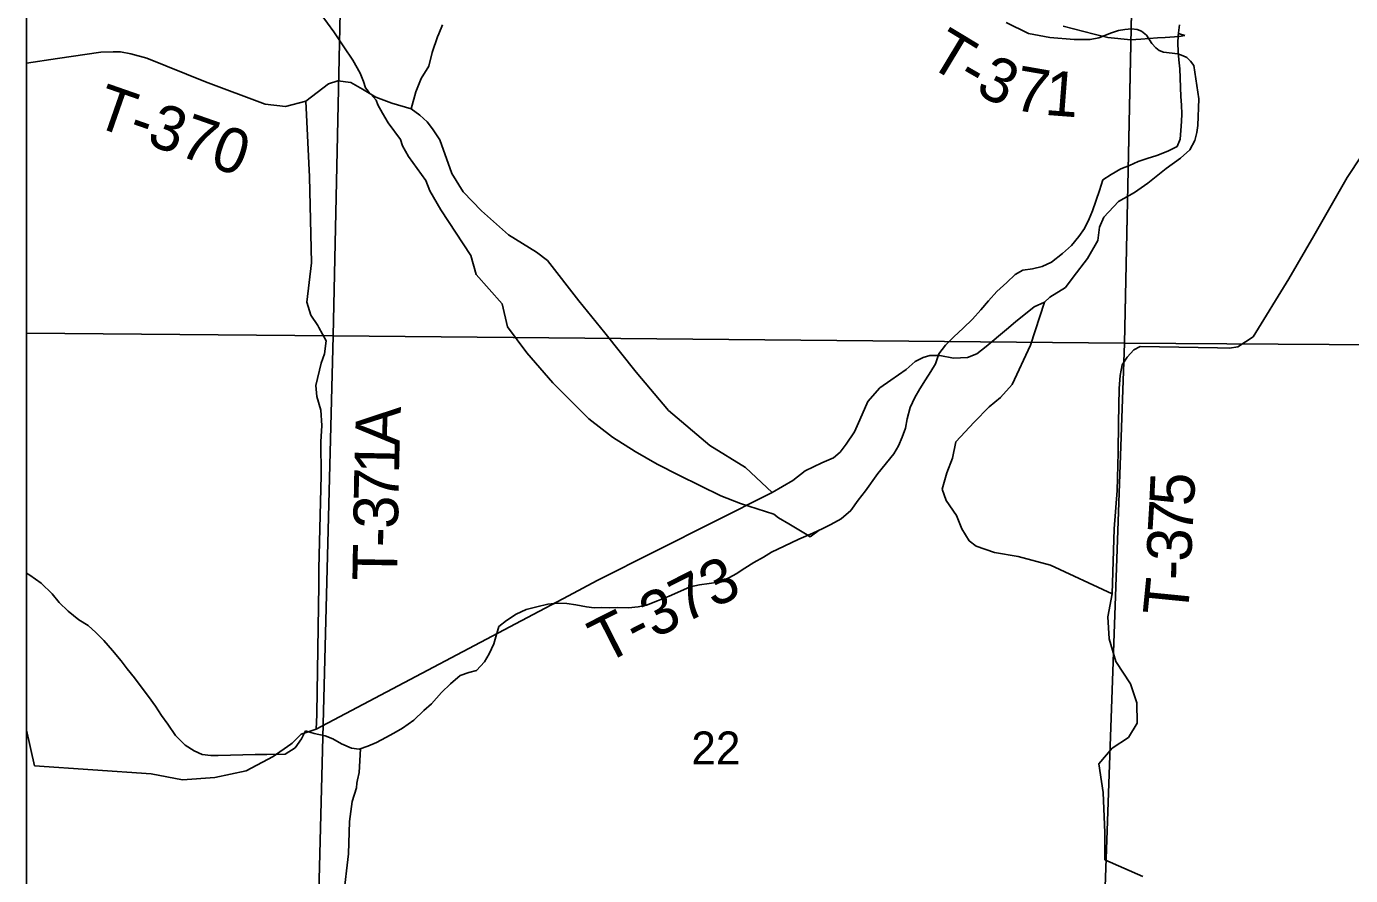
# Model space of a CAD drawing. Extents: x 2.1 to 8.9, y 14.1 to 20.9.
# Drawn here: x 2.1 to 3.78, y 16.441 to 17.519 of the extents above; entities that cross this region are included whole.
import ezdxf

# ---------------------------------------------------------------- set-up
doc = ezdxf.new("R2010")
doc.units = 0
for name, color, linetype in [('Default', 7, 'Continuous'), ('GM_X_City_Street', 7, 'Continuous'), ('GM_X_County_Road_Text', 7, 'Continuous'), ('GM_X_Interchange_Ramps', 7, 'Continuous'), ('GM_X_Minor_River_Text', 7, 'Continuous'), ('SH_Cut_Line', 7, 'Continuous'), ('SH_Data', 7, 'Continuous'), ('TX_P_Misc', 7, 'Continuous')]:
    doc.layers.add(name, color=color, linetype=linetype)

msp = doc.modelspace()

# ---------------------------------------------------------------- linework, layer by layer
at = {"layer": 'Default'}
for p, q in [((2.1, 19.1502), (2.1, 14.1)), ((2.1, 18.1363), (2.1, 17.1299)), ((2.4891, 17.1265), (2.5107, 18.1291)), ((2.1, 17.1299), (2.4891, 17.1265)), ((2.1, 17.1299), (2.1, 16.1234)), ((2.4891, 17.1265), (2.1, 17.1299)), ((2.4631, 16.1204), (2.4891, 17.1265))]:
    msp.add_line(p, q, dxfattribs=at)
at = {"layer": 'GM_X_City_Street'}
for p, q in [((2.6217, 17.5059), (2.6233, 17.5099)), ((2.6233, 17.5099), (2.6278, 17.521)), ((3.3715, 17.5102), (3.3432, 17.5241)), ((3.3989, 17.5049), (3.3715, 17.5102)), ((3.4771, 17.5108), (3.461, 17.5045)), ((3.4861, 17.5139), (3.4771, 17.5108)), ((3.494, 17.5153), (3.4861, 17.5139)), ((3.5026, 17.5161), (3.494, 17.5153)), ((3.5097, 17.5154), (3.5026, 17.5161)), ((3.5153, 17.5131), (3.5097, 17.5154)), ((3.5213, 17.5079), (3.5153, 17.5131)), ((2.615, 17.4862), (2.6217, 17.5059)), ((3.4297, 17.5025), (3.3989, 17.5049)), ((3.4498, 17.5025), (3.4297, 17.5025)), ((3.461, 17.5045), (3.4498, 17.5025)), ((3.5282, 17.4974), (3.5213, 17.5079)), ((3.5335, 17.4919), (3.5282, 17.4974)), ((2.1394, 17.4785), (2.1, 17.4724)), ((2.1944, 17.4865), (2.1394, 17.4785)), ((2.2101, 17.487), (2.1944, 17.4865)), ((2.2193, 17.4867), (2.2101, 17.487)), ((2.2326, 17.4843), (2.2193, 17.4867)), ((2.2526, 17.479), (2.2326, 17.4843)), ((2.3273, 17.4489), (2.2526, 17.479)), ((2.6105, 17.4685), (2.615, 17.4862)), ((3.5374, 17.4887), (3.5335, 17.4919)), ((3.5432, 17.4866), (3.5374, 17.4887)), ((3.5614, 17.4844), (3.5432, 17.4866)), ((3.5678, 17.4819), (3.5614, 17.4844)), ((3.5725, 17.4795), (3.5678, 17.4819)), ((3.5774, 17.4749), (3.5725, 17.4795)), ((2.6009, 17.4529), (2.6105, 17.4685)), ((3.5816, 17.4694), (3.5774, 17.4749)), ((3.5879, 17.4274), (3.5816, 17.4694)), ((2.4031, 17.4204), (2.3273, 17.4489)), ((2.4835, 17.4462), (2.4545, 17.4244)), ((2.4951, 17.4499), (2.4835, 17.4462)), ((2.5118, 17.4479), (2.4951, 17.4499)), ((2.5265, 17.4395), (2.5118, 17.4479)), ((2.5941, 17.4362), (2.6009, 17.4529)), ((2.5434, 17.4293), (2.5265, 17.4395)), ((2.5635, 17.4218), (2.5434, 17.4293)), ((2.5883, 17.4145), (2.5941, 17.4362)), ((3.5867, 17.3933), (3.5879, 17.4274)), ((2.4289, 17.4175), (2.4031, 17.4204)), ((2.4545, 17.4244), (2.4289, 17.4175)), ((2.4591, 17.3283), (2.4545, 17.4244)), ((2.5883, 17.4145), (2.5635, 17.4218)), ((2.5993, 17.4066), (2.5883, 17.4145)), ((2.6084, 17.3978), (2.5993, 17.4066)), ((2.6154, 17.3892), (2.6084, 17.3978)), ((3.5853, 17.3844), (3.5867, 17.3933)), ((2.6248, 17.3751), (2.6154, 17.3892)), ((2.6397, 17.3322), (2.6248, 17.3751)), ((3.5829, 17.3741), (3.5853, 17.3844)), ((3.5647, 17.3517), (3.5766, 17.3623)), ((3.5766, 17.3623), (3.5829, 17.3741)), ((3.5466, 17.3389), (3.5647, 17.3517)), ((3.7763, 17.3273), (3.7944, 17.3548)), ((2.4617, 17.2192), (2.4591, 17.3283)), ((2.654, 17.3092), (2.6397, 17.3322)), ((3.5231, 17.32), (3.5466, 17.3389)), ((3.7337, 17.2533), (3.7763, 17.3273)), ((2.6776, 17.2851), (2.654, 17.3092)), ((3.4859, 17.2969), (3.5061, 17.3084)), ((3.5061, 17.3084), (3.5231, 17.32)), ((3.4675, 17.2768), (3.4859, 17.2969)), ((2.7116, 17.2547), (2.6776, 17.2851)), ((3.4617, 17.2644), (3.4675, 17.2768)), ((3.4598, 17.2472), (3.4617, 17.2644)), ((2.7471, 17.2326), (2.7116, 17.2547)), ((3.4464, 17.2246), (3.4598, 17.2472)), ((3.7021, 17.1987), (3.7337, 17.2533)), ((2.7611, 17.2218), (2.7471, 17.2326)), ((3.4285, 17.201), (3.4464, 17.2246)), ((2.4556, 17.1692), (2.4617, 17.2192)), ((2.8011, 17.1708), (2.7611, 17.2218)), ((3.4185, 17.1876), (3.4285, 17.201)), ((3.6567, 17.1251), (3.7021, 17.1987)), ((3.3919, 17.1689), (3.3986, 17.1753)), ((3.3986, 17.1753), (3.4185, 17.1876)), ((2.4609, 17.1527), (2.4556, 17.1692)), ((2.8338, 17.1301), (2.8011, 17.1708)), ((3.3787, 17.1631), (3.3553, 17.1442)), ((3.3742, 17.1145), (3.3919, 17.1689)), ((3.3919, 17.1689), (3.3787, 17.1631)), ((2.4698, 17.1395), (2.4609, 17.1527)), ((3.3553, 17.1442), (3.3439, 17.1343)), ((2.4711, 17.1371), (2.4698, 17.1395)), ((2.4805, 17.1198), (2.4711, 17.1371)), ((2.8737, 17.0804), (2.8338, 17.1301)), ((3.3439, 17.1343), (3.3179, 17.1129)), ((3.6375, 17.1124), (3.6567, 17.1251)), ((2.4782, 17.1033), (2.4805, 17.1198)), ((3.3179, 17.1129), (3.3063, 17.1036)), ((3.3511, 17.0644), (3.3742, 17.1145)), ((3.4968, 17.0992), (3.5054, 17.1087)), ((3.5054, 17.1087), (3.5133, 17.1127)), ((3.5133, 17.1127), (3.6117, 17.111)), ((3.6117, 17.111), (3.6266, 17.1107)), ((3.6266, 17.1107), (3.6375, 17.1124)), ((2.4671, 17.0633), (2.4738, 17.0917)), ((2.4738, 17.0917), (2.4782, 17.1033)), ((3.2279, 17.0937), (3.2165, 17.0837)), ((3.238, 17.099), (3.2279, 17.0937)), ((3.2465, 17.1013), (3.238, 17.099)), ((3.2592, 17.1013), (3.2465, 17.1013)), ((3.2764, 17.0981), (3.2592, 17.1013)), ((3.2943, 17.0988), (3.2764, 17.0981)), ((3.3063, 17.1036), (3.2943, 17.0988)), ((3.488, 17.0758), (3.4905, 17.0895)), ((3.4905, 17.0895), (3.4968, 17.0992)), ((2.915, 17.0316), (2.8737, 17.0804)), ((3.2165, 17.0837), (3.197, 17.0702)), ((3.4867, 17.0596), (3.488, 17.0758)), ((2.4684, 17.0493), (2.4671, 17.0633)), ((3.1831, 17.0605), (3.1679, 17.0431)), ((3.197, 17.0702), (3.1831, 17.0605)), ((3.3361, 17.0482), (3.3511, 17.0644)), ((3.4861, 17.0159), (3.4867, 17.0596)), ((2.4734, 17.032), (2.4684, 17.0493)), ((3.1679, 17.0431), (3.1576, 17.0199)), ((3.3219, 17.0362), (3.3361, 17.0482)), ((2.475, 17.0127), (2.4734, 17.032)), ((2.9674, 16.9872), (2.915, 17.0316)), ((3.3027, 17.0167), (3.3219, 17.0362)), ((2.4736, 16.9917), (2.475, 17.0127)), ((3.1576, 17.0199), (3.1509, 17.0045)), ((3.2796, 16.9917), (3.3027, 17.0167)), ((3.4855, 16.9781), (3.4861, 17.0159)), ((2.4739, 16.9495), (2.4736, 16.9917)), ((3.1401, 16.9887), (3.1328, 16.9785)), ((3.1509, 17.0045), (3.1401, 16.9887)), ((3.2752, 16.9712), (3.2796, 16.9917)), ((3.0126, 16.9593), (2.9674, 16.9872)), ((3.1328, 16.9785), (3.1241, 16.9715)), ((3.4841, 16.9301), (3.4855, 16.9781)), ((3.0465, 16.9274), (3.0126, 16.9593)), ((3.1094, 16.9649), (3.0883, 16.9548)), ((3.1241, 16.9715), (3.1094, 16.9649)), ((3.2681, 16.9524), (3.2752, 16.9712)), ((2.4712, 16.8304), (2.4739, 16.9495)), ((3.0725, 16.9426), (3.0465, 16.9274)), ((3.0883, 16.9548), (3.0725, 16.9426)), ((3.262, 16.9316), (3.2681, 16.9524)), ((2.8242, 16.8156), (3.0465, 16.9274)), ((3.2673, 16.9171), (3.262, 16.9316)), ((3.4805, 16.8814), (3.4841, 16.9301)), ((3.2802, 16.8984), (3.2673, 16.9171)), ((3.287, 16.8814), (3.2802, 16.8984)), ((3.2966, 16.8659), (3.287, 16.8814)), ((3.478, 16.799), (3.4805, 16.8814)), ((3.3053, 16.8593), (3.2966, 16.8659)), ((3.3287, 16.8512), (3.3053, 16.8593)), ((3.3584, 16.846), (3.3287, 16.8512)), ((3.3995, 16.8354), (3.3584, 16.846)), ((2.4709, 16.8102), (2.4712, 16.8304)), ((3.478, 16.799), (3.3995, 16.8354)), ((2.4687, 16.647), (2.4709, 16.8102)), ((2.7877, 16.7963), (2.8242, 16.8156)), ((2.4675, 16.627), (2.7877, 16.7963)), ((3.4723, 16.7698), (3.478, 16.799)), ((3.4739, 16.7415), (3.4723, 16.7698)), ((3.4824, 16.7127), (3.4739, 16.7415)), ((3.5011, 16.6844), (3.4824, 16.7127)), ((3.5091, 16.6603), (3.5011, 16.6844)), ((3.5097, 16.6347), (3.5091, 16.6603)), ((2.4675, 16.627), (2.4685, 16.6452)), ((2.4685, 16.6452), (2.4687, 16.647)), ((2.1, 16.6259), (2.1102, 16.5805)), ((2.4395, 16.6115), (2.4487, 16.6205)), ((2.4487, 16.6205), (2.4675, 16.627)), ((3.4984, 16.6165), (3.5097, 16.6347)), ((2.413, 16.5924), (2.4356, 16.6081)), ((2.4356, 16.6081), (2.4372, 16.6093)), ((2.4372, 16.6093), (2.4395, 16.6115)), ((3.4609, 16.583), (3.4778, 16.6029)), ((3.4778, 16.6029), (3.4984, 16.6165)), ((2.3789, 16.5742), (2.413, 16.5924)), ((2.1102, 16.5805), (2.2583, 16.5702)), ((2.2583, 16.5702), (2.2978, 16.5627)), ((2.339, 16.5658), (2.3789, 16.5742)), ((3.4643, 16.5605), (3.4609, 16.583)), ((2.2978, 16.5627), (2.339, 16.5658)), ((3.4665, 16.5468), (3.4643, 16.5605)), ((3.4685, 16.4953), (3.4665, 16.5468)), ((3.4685, 16.4612), (3.4685, 16.4953)), ((3.517, 16.4401), (3.4685, 16.4612))]:
    msp.add_line(p, q, dxfattribs=at)
at = {"layer": 'GM_X_Interchange_Ramps'}
for p, q in [((2.4891, 17.1265), (2.5107, 18.1291)), ((3.5154, 18.1224), (3.4934, 17.1171)), ((3.4934, 17.1171), (3.5154, 18.1224)), ((2.4631, 16.1204), (2.4891, 17.1265)), ((3.4934, 17.1171), (2.4891, 17.1265)), ((2.4891, 17.1265), (3.4934, 17.1171)), ((3.4934, 17.1171), (3.4577, 16.1051)), ((3.4577, 16.1051), (3.4934, 17.1171)), ((4.4928, 17.1099), (3.4934, 17.1171)), ((3.4934, 17.1171), (4.4928, 17.1099))]:
    msp.add_line(p, q, dxfattribs=at)
at = {"layer": 'SH_Cut_Line'}
msp.add_line((2.1, 20.9), (2.1, 14.1), dxfattribs=at)
at = {"layer": 'SH_Data'}
msp.add_line((2.1, 20.9), (2.1, 14.1), dxfattribs=at)
msp.add_line((2.1, 20.9), (2.1, 14.1), dxfattribs=at)
at = {"layer": 'TX_P_Misc'}
for p, q in [((2.4899, 17.5123), (2.474, 17.5344)), ((2.5027, 17.4931), (2.4899, 17.5123)), ((3.455, 17.5091), (3.4159, 17.5195)), ((3.5635, 17.5211), (3.5616, 17.5074)), ((3.562, 17.51), (3.5699, 17.5076)), ((2.5143, 17.4761), (2.5027, 17.4931)), ((3.4724, 17.5052), (3.455, 17.5091)), ((3.5016, 17.5019), (3.4724, 17.5052)), ((3.5144, 17.5029), (3.5016, 17.5019)), ((3.5352, 17.5047), (3.5144, 17.5029)), ((3.545, 17.5049), (3.5352, 17.5047)), ((3.5628, 17.5063), (3.545, 17.5049)), ((3.5616, 17.5074), (3.5612, 17.4979)), ((3.5612, 17.4979), (3.5615, 17.4872)), ((3.5699, 17.5076), (3.5628, 17.5063)), ((2.5233, 17.4599), (2.5143, 17.4761)), ((3.5615, 17.4872), (3.5626, 17.4766)), ((3.5626, 17.4766), (3.5637, 17.4652)), ((2.5276, 17.4493), (2.5233, 17.4599)), ((3.5637, 17.4652), (3.564, 17.4538)), ((2.5304, 17.441), (2.5276, 17.4493)), ((3.564, 17.4538), (3.5648, 17.4416)), ((2.5335, 17.4369), (2.5304, 17.441)), ((2.5439, 17.4256), (2.5335, 17.4369)), ((2.5459, 17.4196), (2.5439, 17.4256)), ((3.5648, 17.4416), (3.5651, 17.4302)), ((3.5651, 17.4302), (3.5659, 17.4192)), ((2.5518, 17.409), (2.5459, 17.4196)), ((2.5592, 17.3969), (2.5518, 17.409)), ((3.5659, 17.4192), (3.5662, 17.4082)), ((2.5746, 17.3755), (2.5592, 17.3969)), ((3.5657, 17.3986), (3.5649, 17.3872)), ((3.5662, 17.4082), (3.5657, 17.3986)), ((2.5771, 17.3675), (2.5746, 17.3755)), ((3.5641, 17.3761), (3.5603, 17.3665)), ((3.5649, 17.3872), (3.5641, 17.3761)), ((2.5848, 17.354), (2.5771, 17.3675)), ((3.5486, 17.3608), (3.5344, 17.3554)), ((3.5603, 17.3665), (3.5486, 17.3608)), ((2.6069, 17.3235), (2.5848, 17.354)), ((3.4998, 17.3425), (3.4889, 17.3384)), ((3.511, 17.3478), (3.4998, 17.3425)), ((3.5223, 17.3516), (3.511, 17.3478)), ((3.5344, 17.3554), (3.5223, 17.3516)), ((3.4766, 17.3311), (3.4661, 17.3243)), ((3.4889, 17.3384), (3.4766, 17.3311)), ((2.6117, 17.3103), (2.6069, 17.3235)), ((2.6257, 17.2861), (2.6117, 17.3103)), ((3.462, 17.3109), (3.4529, 17.2851)), ((3.4661, 17.3243), (3.462, 17.3109)), ((2.6641, 17.2282), (2.6257, 17.2861)), ((3.4486, 17.2747), (3.4426, 17.2627)), ((3.4529, 17.2851), (3.4486, 17.2747)), ((3.4426, 17.2627), (3.4356, 17.2526)), ((3.4261, 17.2412), (3.415, 17.231)), ((3.4356, 17.2526), (3.4261, 17.2412)), ((2.6709, 17.2043), (2.6641, 17.2282)), ((3.415, 17.231), (3.4009, 17.2199)), ((3.3643, 17.2096), (3.3546, 17.204)), ((3.3768, 17.2115), (3.3643, 17.2096)), ((3.3889, 17.2142), (3.3768, 17.2115)), ((3.4009, 17.2199), (3.3889, 17.2142)), ((2.7037, 17.1668), (2.6709, 17.2043)), ((3.3443, 17.1941), (3.3317, 17.1827)), ((3.3546, 17.204), (3.3443, 17.1941)), ((3.3317, 17.1827), (3.3211, 17.1706)), ((2.7106, 17.1376), (2.7037, 17.1668)), ((3.3112, 17.1592), (3.3005, 17.1474)), ((3.3211, 17.1706), (3.3112, 17.1592)), ((3.3005, 17.1474), (3.2887, 17.136)), ((2.735, 17.1049), (2.7106, 17.1376)), ((3.2768, 17.125), (3.2665, 17.1144)), ((3.2887, 17.136), (3.2768, 17.125)), ((3.2665, 17.1144), (3.2577, 17.1035)), ((2.7678, 17.0666), (2.735, 17.1049)), ((3.2536, 17.0908), (3.2478, 17.0811)), ((3.2577, 17.1035), (3.2536, 17.0908)), ((3.2478, 17.0811), (3.2409, 17.0706)), ((2.8136, 17.0209), (2.7678, 17.0666)), ((3.2336, 17.0589), (3.2275, 17.0481)), ((3.2409, 17.0706), (3.2336, 17.0589)), ((3.2275, 17.0481), (3.2214, 17.0353)), ((3.2214, 17.0353), (3.2177, 17.0211)), ((2.8438, 16.9975), (2.8136, 17.0209)), ((3.2154, 17.0092), (3.2112, 16.9977)), ((3.2177, 17.0211), (3.2154, 17.0092)), ((2.8725, 16.9793), (2.8438, 16.9975)), ((3.2112, 16.9977), (3.2066, 16.9865)), ((2.9004, 16.9634), (2.8725, 16.9793)), ((3.2008, 16.9764), (3.1803, 16.9514)), ((3.2066, 16.9865), (3.2008, 16.9764)), ((2.9278, 16.9494), (2.9004, 16.9634)), ((2.9553, 16.9361), (2.9278, 16.9494)), ((3.1803, 16.9514), (3.165, 16.9296)), ((2.9812, 16.9232), (2.9553, 16.9361)), ((3.0063, 16.9134), (2.9812, 16.9232)), ((3.165, 16.9296), (3.1555, 16.9175)), ((3.0485, 16.9), (3.0063, 16.9134)), ((3.146, 16.9047), (3.1338, 16.894)), ((3.1555, 16.9175), (3.146, 16.9047)), ((3.0543, 16.8951), (3.0485, 16.9)), ((3.0676, 16.8878), (3.0543, 16.8951)), ((3.1338, 16.894), (3.1207, 16.8867)), ((3.0886, 16.8748), (3.0676, 16.8878)), ((3.0978, 16.8757), (3.0802, 16.868)), ((3.0944, 16.8711), (3.0886, 16.8748)), ((3.1062, 16.8798), (3.0944, 16.8711)), ((3.1106, 16.8819), (3.0978, 16.8757)), ((3.1207, 16.8867), (3.1106, 16.8819)), ((3.0615, 16.8594), (3.0457, 16.8516)), ((3.0802, 16.868), (3.0615, 16.8594)), ((3.0229, 16.8387), (3.0117, 16.8315)), ((3.0353, 16.8452), (3.0229, 16.8387)), ((3.0457, 16.8516), (3.0353, 16.8452)), ((2.1041, 16.8224), (2.1, 16.8249)), ((2.1185, 16.8122), (2.1041, 16.8224)), ((3.0006, 16.824), (2.9875, 16.8171)), ((3.0117, 16.8315), (3.0006, 16.824)), ((2.1326, 16.799), (2.1185, 16.8122)), ((2.9425, 16.8077), (2.9301, 16.8023)), ((2.9542, 16.8103), (2.9425, 16.8077)), ((2.9663, 16.8118), (2.9542, 16.8103)), ((2.9777, 16.8137), (2.9663, 16.8118)), ((2.9875, 16.8171), (2.9777, 16.8137)), ((2.1413, 16.7878), (2.1326, 16.799)), ((2.1527, 16.7767), (2.1413, 16.7878)), ((2.9009, 16.79), (2.887, 16.7846)), ((2.9155, 16.7958), (2.9009, 16.79)), ((2.9301, 16.8023), (2.9155, 16.7958)), ((2.1663, 16.7658), (2.1527, 16.7767)), ((2.7216, 16.7729), (2.7093, 16.7649)), ((2.7343, 16.7791), (2.7216, 16.7729)), ((2.7475, 16.7825), (2.7343, 16.7791)), ((2.7618, 16.7856), (2.7475, 16.7825)), ((2.7747, 16.7868), (2.7618, 16.7856)), ((2.7858, 16.7864), (2.7747, 16.7868)), ((2.7972, 16.7848), (2.7858, 16.7864)), ((2.8106, 16.7822), (2.7972, 16.7848)), ((2.8205, 16.781), (2.8106, 16.7822)), ((2.83, 16.7813), (2.8205, 16.781)), ((2.8403, 16.7812), (2.83, 16.7813)), ((2.8506, 16.7816), (2.8403, 16.7812)), ((2.8639, 16.7812), (2.8506, 16.7816)), ((2.8764, 16.7824), (2.8639, 16.7812)), ((2.887, 16.7846), (2.8764, 16.7824)), ((2.1783, 16.7585), (2.1663, 16.7658)), ((2.1881, 16.7497), (2.1783, 16.7585)), ((2.6996, 16.7574), (2.693, 16.7355)), ((2.7093, 16.7649), (2.6996, 16.7574)), ((2.1983, 16.7397), (2.1881, 16.7497)), ((2.2093, 16.7267), (2.1983, 16.7397)), ((2.22, 16.7138), (2.2093, 16.7267)), ((2.687, 16.7227), (2.6812, 16.7123)), ((2.693, 16.7355), (2.687, 16.7227)), ((2.2279, 16.7037), (2.22, 16.7138)), ((2.237, 16.6922), (2.2279, 16.7037)), ((2.6812, 16.7123), (2.6713, 16.7013)), ((2.2457, 16.6807), (2.237, 16.6922)), ((2.6506, 16.6953), (2.638, 16.6847)), ((2.6615, 16.6991), (2.6506, 16.6953)), ((2.6713, 16.7013), (2.6615, 16.6991)), ((2.2548, 16.6684), (2.2457, 16.6807)), ((2.6269, 16.6736), (2.614, 16.6592)), ((2.638, 16.6847), (2.6269, 16.6736)), ((2.2636, 16.6561), (2.2548, 16.6684)), ((2.2715, 16.6442), (2.2636, 16.6561)), ((2.614, 16.6592), (2.6044, 16.6505)), ((2.2795, 16.6334), (2.2715, 16.6442)), ((2.5915, 16.6386), (2.5773, 16.6283)), ((2.6044, 16.6505), (2.5915, 16.6386)), ((2.2891, 16.6188), (2.2795, 16.6334)), ((2.4543, 16.6248), (2.4492, 16.6148)), ((2.465, 16.6217), (2.4543, 16.6248)), ((2.4792, 16.6184), (2.465, 16.6217)), ((2.5661, 16.6219), (2.556, 16.6166)), ((2.5773, 16.6283), (2.5661, 16.6219)), ((2.3012, 16.6067), (2.2891, 16.6188)), ((2.3128, 16.5994), (2.3012, 16.6067)), ((2.4409, 16.6031), (2.4282, 16.5954)), ((2.4492, 16.6148), (2.4409, 16.6031)), ((2.4888, 16.6149), (2.4792, 16.6184)), ((2.5, 16.6084), (2.4888, 16.6149)), ((2.5123, 16.603), (2.5, 16.6084)), ((2.5223, 16.6014), (2.5123, 16.603)), ((2.5332, 16.6056), (2.5223, 16.6014)), ((2.5441, 16.6101), (2.5332, 16.6056)), ((2.556, 16.6166), (2.5441, 16.6101)), ((2.3229, 16.5948), (2.3128, 16.5994)), ((2.3339, 16.5936), (2.3229, 16.5948)), ((2.3434, 16.5935), (2.3339, 16.5936)), ((2.3902, 16.595), (2.3434, 16.5935)), ((2.405, 16.5947), (2.3902, 16.595)), ((2.4282, 16.5954), (2.405, 16.5947)), ((2.5239, 16.6021), (2.5223, 16.572)), ((2.5223, 16.572), (2.5202, 16.5628)), ((2.5188, 16.5525), (2.5134, 16.5353)), ((2.5191, 16.5586), (2.5188, 16.5525)), ((2.5202, 16.5628), (2.5191, 16.5586)), ((2.5134, 16.5353), (2.5101, 16.5097)), ((2.5101, 16.5097), (2.5085, 16.4686)), ((2.5085, 16.4686), (2.5023, 16.4145))]:
    msp.add_line(p, q, dxfattribs=at)

# ---------------------------------------------------------------- texts
at = {"layer": 'GM_X_County_Road_Text'}
msp.add_text('22', height=0.04186, rotation=0, dxfattribs=at).set_placement((2.9438, 16.5822))
at = {"layer": 'GM_X_Minor_River_Text'}
for s, height, rotation, p in [('T', 0.0568, 328.8782, (3.2414, 17.4708)), ('3', 0.0568, 333.8375, (3.3027, 17.4346)), ('-', 0.0568, 330.0266, (3.2789, 17.4482)), ('7', 0.0568, 350.1359, (3.3509, 17.4138)), ('1', 0.0568, 355.5926, (3.3912, 17.407)), ('T-370', 0.05682, 340.7819, (2.1831, 17.3935)), ('A', 0.0568, 88.007, (2.5735, 16.9857)), ('1', 0.0568, 88.7978, (2.5728, 16.9509)), ('7', 0.0568, 88.9591, (2.5721, 16.916)), ('5', 0.0568, 87.2987, (3.5816, 16.9094)), ('3', 0.0568, 89.0164, (2.5715, 16.881)), ('7', 0.0568, 86.5373, (3.5795, 16.8737)), ('-', 0.0568, 89.0326, (2.5712, 16.8577)), ('3', 0.0568, 87.9752, (3.5783, 16.8391)), ('T', 0.0568, 89.0228, (2.5704, 16.8152)), ('T-373', 0.05682, 26.9405, (2.8333, 16.709)), ('-', 0.0568, 88.4418, (3.5776, 16.8159)), ('T', 0.0568, 84.3295, (3.5732, 16.7691))]:
    msp.add_text(s, height=height, rotation=rotation, dxfattribs=at).set_placement(p)

doc.saveas('drawing.dxf')
